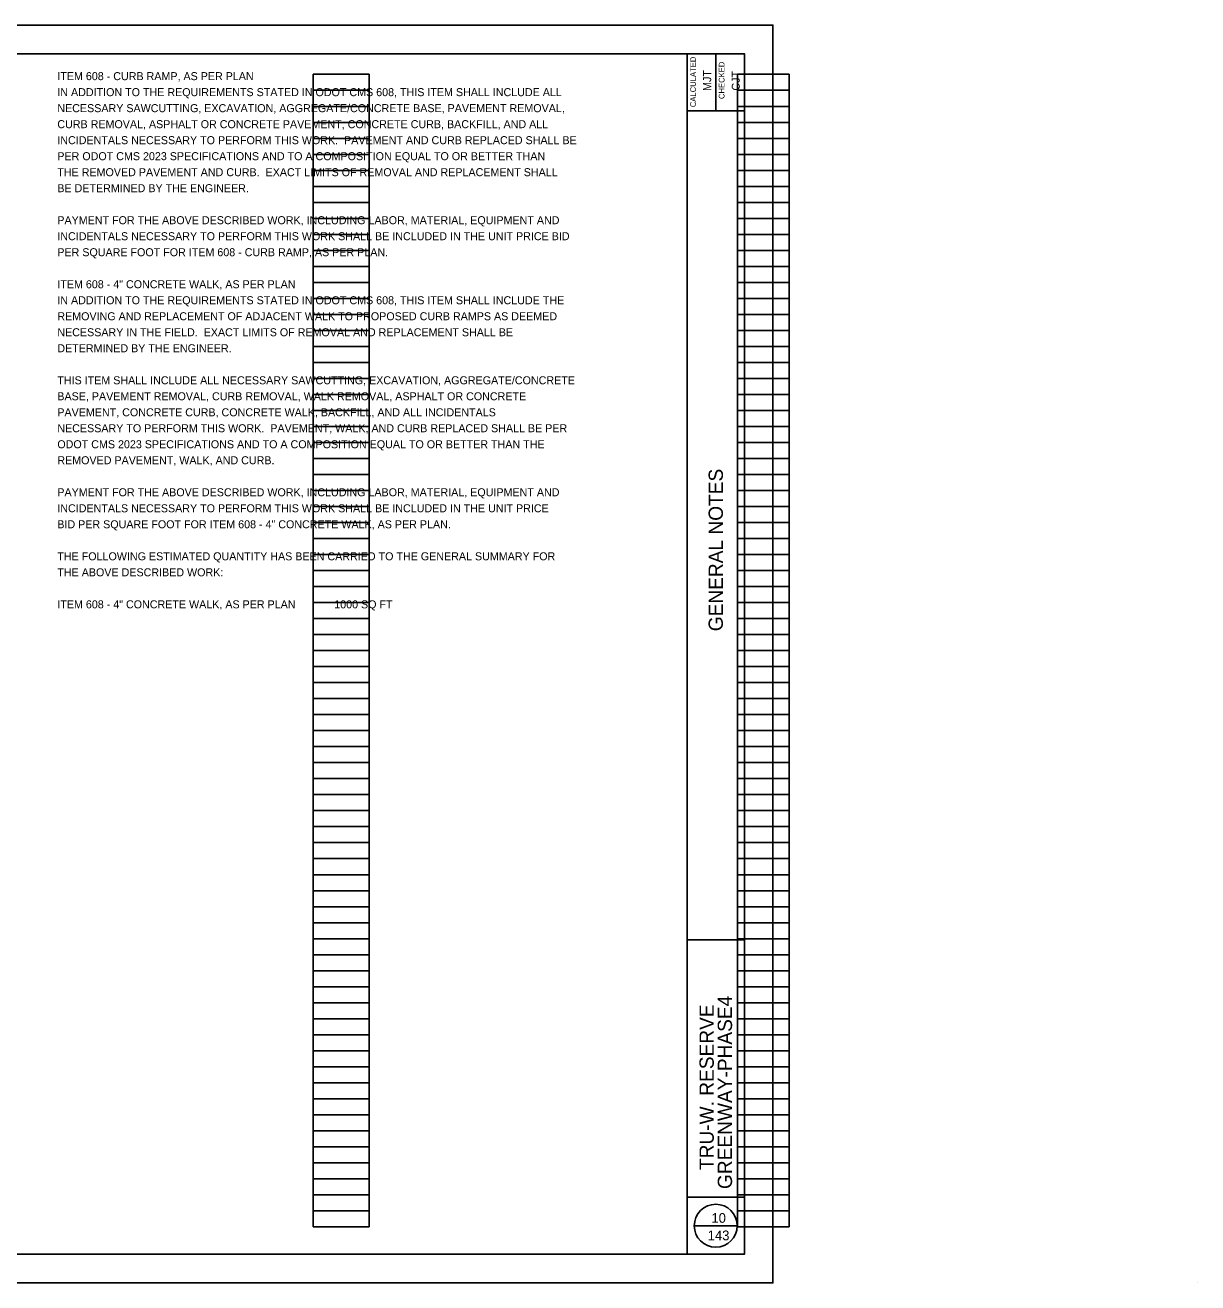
# Model space of a CAD drawing. Extents: x -16 to 195, y -13 to 9.
# Drawn here: x 48.79 to 69.29, y -12.91 to 9.09 of the extents above; entities that cross this region are included whole.
import ezdxf

# ---------------------------------------------------------------- set-up
doc = ezdxf.new("R2010")
doc.units = 0
for name, color, linetype in [('SH_Border', 7, 'Continuous'), ('SH_Cut_Line', 7, 'Continuous'), ('SH_Data', 7, 'Continuous'), ('TX_P_1', 7, 'Continuous')]:
    doc.layers.add(name, color=color, linetype=linetype)

msp = doc.modelspace()

# ---------------------------------------------------------------- linework, layer by layer
at = {"layer": 'SH_Border'}
for p, q in [((60.361, -12.407), (60.361, 8.593)), ((60.861, 8.593), (60.861, 7.593)), ((60.361, 7.593), (61.361, 7.593)), ((60.361, -6.907), (61.361, -6.907)), ((60.361, -11.407), (61.361, -11.407))]:
    msp.add_line(p, q, dxfattribs=at)
msp.add_lwpolyline([(29.861, 8.593), (61.361, 8.593), (61.361, -12.407), (29.861, -12.407)], close=True, dxfattribs=at)
at = {"layer": 'SH_Cut_Line'}
msp.add_lwpolyline([(27.861, -12.907), (61.861, -12.907), (61.861, 9.093), (27.861, 9.093)], close=True, dxfattribs=at)
at = {"layer": 'SH_Data'}
for p, q in [((53.822, -11.927), (53.822, 8.233)), ((53.822, 8.233), (54.802, 8.233)), ((54.802, -11.927), (54.802, 8.233)), ((61.242, -11.927), (61.242, 8.233)), ((61.242, 8.233), (62.142, 8.233)), ((62.142, -11.927), (62.142, 8.233)), ((53.822, 7.953), (54.802, 7.953)), ((61.242, 7.953), (62.142, 7.953)), ((53.822, 7.673), (54.802, 7.673)), ((61.242, 7.673), (62.142, 7.673)), ((53.822, 7.393), (54.802, 7.393)), ((61.242, 7.393), (62.142, 7.393)), ((53.822, 7.113), (54.802, 7.113)), ((61.242, 7.113), (62.142, 7.113)), ((53.822, 6.833), (54.802, 6.833)), ((61.242, 6.833), (62.142, 6.833)), ((53.822, 6.553), (54.802, 6.553)), ((61.242, 6.553), (62.142, 6.553)), ((53.822, 6.273), (54.802, 6.273)), ((61.242, 6.273), (62.142, 6.273)), ((53.822, 5.993), (54.802, 5.993)), ((61.242, 5.993), (62.142, 5.993)), ((53.822, 5.713), (54.802, 5.713)), ((61.242, 5.713), (62.142, 5.713)), ((53.822, 5.433), (54.802, 5.433)), ((61.242, 5.433), (62.142, 5.433)), ((53.822, 5.153), (54.802, 5.153)), ((61.242, 5.153), (62.142, 5.153)), ((53.822, 4.873), (54.802, 4.873)), ((61.242, 4.873), (62.142, 4.873)), ((53.822, 4.593), (54.802, 4.593)), ((61.242, 4.593), (62.142, 4.593)), ((53.822, 4.313), (54.802, 4.313)), ((61.242, 4.313), (62.142, 4.313)), ((53.822, 4.033), (54.802, 4.033)), ((61.242, 4.033), (62.142, 4.033)), ((53.822, 3.753), (54.802, 3.753)), ((61.242, 3.753), (62.142, 3.753)), ((53.822, 3.473), (54.802, 3.473)), ((61.242, 3.473), (62.142, 3.473)), ((53.822, 3.193), (54.802, 3.193)), ((61.242, 3.193), (62.142, 3.193)), ((53.822, 2.913), (54.802, 2.913)), ((61.242, 2.913), (62.142, 2.913)), ((53.822, 2.633), (54.802, 2.633)), ((61.242, 2.633), (62.142, 2.633)), ((53.822, 2.353), (54.802, 2.353)), ((61.242, 2.353), (62.142, 2.353)), ((53.822, 2.073), (54.802, 2.073)), ((61.242, 2.073), (62.142, 2.073)), ((53.822, 1.793), (54.802, 1.793)), ((61.242, 1.793), (62.142, 1.793)), ((53.822, 1.513), (54.802, 1.513)), ((61.242, 1.513), (62.142, 1.513)), ((53.822, 1.233), (54.802, 1.233)), ((61.242, 1.233), (62.142, 1.233)), ((53.822, 0.953), (54.802, 0.953)), ((61.242, 0.953), (62.142, 0.953)), ((53.822, 0.673), (54.802, 0.673)), ((61.242, 0.673), (62.142, 0.673)), ((53.822, 0.393), (54.802, 0.393)), ((61.242, 0.393), (62.142, 0.393)), ((53.822, 0.113), (54.802, 0.113)), ((61.242, 0.113), (62.142, 0.113)), ((53.822, -0.167), (54.802, -0.167)), ((61.242, -0.167), (62.142, -0.167)), ((53.822, -0.447), (54.802, -0.447)), ((61.242, -0.447), (62.142, -0.447)), ((53.822, -0.727), (54.802, -0.727)), ((61.242, -0.727), (62.142, -0.727)), ((53.822, -1.007), (54.802, -1.007)), ((61.242, -1.007), (62.142, -1.007)), ((53.822, -1.287), (54.802, -1.287)), ((61.242, -1.287), (62.142, -1.287)), ((53.822, -1.567), (54.802, -1.567)), ((61.242, -1.567), (62.142, -1.567)), ((53.822, -1.847), (54.802, -1.847)), ((61.242, -1.847), (62.142, -1.847)), ((53.822, -2.127), (54.802, -2.127)), ((61.242, -2.127), (62.142, -2.127)), ((53.822, -2.407), (54.802, -2.407)), ((61.242, -2.407), (62.142, -2.407)), ((53.822, -2.687), (54.802, -2.687)), ((61.242, -2.687), (62.142, -2.687)), ((53.822, -2.967), (54.802, -2.967)), ((61.242, -2.967), (62.142, -2.967)), ((53.822, -3.247), (54.802, -3.247)), ((61.242, -3.247), (62.142, -3.247)), ((53.822, -3.527), (54.802, -3.527)), ((61.242, -3.527), (62.142, -3.527)), ((53.822, -3.807), (54.802, -3.807)), ((61.242, -3.807), (62.142, -3.807)), ((53.822, -4.087), (54.802, -4.087)), ((61.242, -4.087), (62.142, -4.087)), ((53.822, -4.367), (54.802, -4.367)), ((61.242, -4.367), (62.142, -4.367)), ((53.822, -4.647), (54.802, -4.647)), ((61.242, -4.647), (62.142, -4.647)), ((53.822, -4.927), (54.802, -4.927)), ((61.242, -4.927), (62.142, -4.927)), ((53.822, -5.207), (54.802, -5.207)), ((61.242, -5.207), (62.142, -5.207)), ((53.822, -5.487), (54.802, -5.487)), ((61.242, -5.487), (62.142, -5.487)), ((53.822, -5.767), (54.802, -5.767)), ((61.242, -5.767), (62.142, -5.767)), ((53.822, -6.047), (54.802, -6.047)), ((61.242, -6.047), (62.142, -6.047)), ((53.822, -6.327), (54.802, -6.327)), ((61.242, -6.327), (62.142, -6.327)), ((53.822, -6.607), (54.802, -6.607)), ((61.242, -6.607), (62.142, -6.607)), ((53.822, -6.887), (54.802, -6.887)), ((61.242, -6.887), (62.142, -6.887)), ((53.822, -7.167), (54.802, -7.167)), ((61.242, -7.167), (62.142, -7.167)), ((53.822, -7.447), (54.802, -7.447)), ((61.242, -7.447), (62.142, -7.447)), ((53.822, -7.727), (54.802, -7.727)), ((61.242, -7.727), (62.142, -7.727)), ((53.822, -8.007), (54.802, -8.007)), ((61.242, -8.007), (62.142, -8.007)), ((53.822, -8.287), (54.802, -8.287)), ((61.242, -8.287), (62.142, -8.287)), ((53.822, -8.567), (54.802, -8.567)), ((61.242, -8.567), (62.142, -8.567)), ((53.822, -8.847), (54.802, -8.847)), ((61.242, -8.847), (62.142, -8.847)), ((53.822, -9.127), (54.802, -9.127)), ((61.242, -9.127), (62.142, -9.127)), ((53.822, -9.407), (54.802, -9.407)), ((61.242, -9.407), (62.142, -9.407)), ((53.822, -9.687), (54.802, -9.687)), ((61.242, -9.687), (62.142, -9.687)), ((53.822, -9.967), (54.802, -9.967)), ((61.242, -9.967), (62.142, -9.967)), ((53.822, -10.247), (54.802, -10.247)), ((61.242, -10.247), (62.142, -10.247)), ((53.822, -10.527), (54.802, -10.527)), ((61.242, -10.527), (62.142, -10.527)), ((53.822, -10.807), (54.802, -10.807)), ((61.242, -10.807), (62.142, -10.807)), ((53.822, -11.087), (54.802, -11.087)), ((61.242, -11.087), (62.142, -11.087)), ((53.822, -11.367), (54.802, -11.367)), ((61.242, -11.367), (62.142, -11.367)), ((53.822, -11.647), (54.802, -11.647)), ((61.242, -11.647), (62.142, -11.647)), ((53.822, -11.927), (54.802, -11.927)), ((60.486, -11.907), (61.236, -11.907)), ((61.242, -11.927), (62.142, -11.927)), ((69.29, -12.907), (69.29, -12.907))]:
    msp.add_line(p, q, dxfattribs=at)
msp.add_circle((60.861, -11.907), 0.375, dxfattribs=at)

# ---------------------------------------------------------------- texts
for s, height, p in [('CALCULATED', 0.1, (60.514, 7.658)), ('CHECKED', 0.1, (61.014, 7.801)), ('MJT', 0.14, (60.781, 7.942)), ('CJT', 0.14, (61.281, 7.949)), ('GENERAL NOTES', 0.25, (60.986, -1.509)), ('GREENWAY-PHASE4', 0.25, (61.146, -11.266)), ('TRU-W. RESERVE', 0.25, (60.827, -10.934))]:
    msp.add_text(s, height=height, rotation=90, dxfattribs=at).set_placement(p)
for s, p in [('10', (60.786, -11.857)), ('143', (60.721, -12.162))]:
    msp.add_text(s, height=0.17, dxfattribs=at).set_placement(p)
at = {"layer": 'TX_P_1'}
for s, p in [('ITEM 608 - CURB RAMP, AS PER PLAN', (49.349, 8.131)), ('IN ADDITION TO THE REQUIREMENTS STATED IN ODOT CMS 608, THIS ITEM SHALL INCLUDE ALL', (49.349, 7.851)), ('NECESSARY SAWCUTTING, EXCAVATION, AGGREGATE/CONCRETE BASE, PAVEMENT REMOVAL,', (49.349, 7.571)), ('CURB REMOVAL, ASPHALT OR CONCRETE PAVEMENT, CONCRETE CURB, BACKFILL, AND ALL', (49.349, 7.291)), ('INCIDENTALS NECESSARY TO PERFORM THIS WORK.  PAVEMENT AND CURB REPLACED SHALL BE', (49.349, 7.011)), ('PER ODOT CMS 2023 SPECIFICATIONS AND TO A COMPOSITION EQUAL TO OR BETTER THAN', (49.349, 6.731)), ('THE REMOVED PAVEMENT AND CURB.  EXACT LIMITS OF REMOVAL AND REPLACEMENT SHALL', (49.349, 6.451)), ('BE DETERMINED BY THE ENGINEER.', (49.349, 6.171)), ('PAYMENT FOR THE ABOVE DESCRIBED WORK, INCLUDING LABOR, MATERIAL, EQUIPMENT AND', (49.349, 5.611)), ('INCIDENTALS NECESSARY TO PERFORM THIS WORK SHALL BE INCLUDED IN THE UNIT PRICE BID', (49.349, 5.331)), ('PER SQUARE FOOT FOR ITEM 608 - CURB RAMP, AS PER PLAN.', (49.349, 5.051)), ('ITEM 608 - 4" CONCRETE WALK, AS PER PLAN', (49.349, 4.491)), ('IN ADDITION TO THE REQUIREMENTS STATED IN ODOT CMS 608, THIS ITEM SHALL INCLUDE THE', (49.349, 4.211)), ('REMOVING AND REPLACEMENT OF ADJACENT WALK TO PROPOSED CURB RAMPS AS DEEMED', (49.349, 3.931)), ('NECESSARY IN THE FIELD.  EXACT LIMITS OF REMOVAL AND REPLACEMENT SHALL BE', (49.349, 3.651)), ('DETERMINED BY THE ENGINEER.', (49.349, 3.371)), ('THIS ITEM SHALL INCLUDE ALL NECESSARY SAWCUTTING, EXCAVATION, AGGREGATE/CONCRETE', (49.349, 2.811)), ('BASE, PAVEMENT REMOVAL, CURB REMOVAL, WALK REMOVAL, ASPHALT OR CONCRETE', (49.349, 2.531)), ('PAVEMENT, CONCRETE CURB, CONCRETE WALK, BACKFILL, AND ALL INCIDENTALS', (49.349, 2.251)), ('NECESSARY TO PERFORM THIS WORK.  PAVEMENT, WALK, AND CURB REPLACED SHALL BE PER', (49.349, 1.972)), ('ODOT CMS 2023 SPECIFICATIONS AND TO A COMPOSITION EQUAL TO OR BETTER THAN THE', (49.349, 1.692)), ('REMOVED PAVEMENT, WALK, AND CURB.  ', (49.349, 1.412)), ('PAYMENT FOR THE ABOVE DESCRIBED WORK, INCLUDING LABOR, MATERIAL, EQUIPMENT AND', (49.349, 0.852)), ('INCIDENTALS NECESSARY TO PERFORM THIS WORK SHALL BE INCLUDED IN THE UNIT PRICE', (49.349, 0.572)), ('BID PER SQUARE FOOT FOR ITEM 608 - 4" CONCRETE WALK, AS PER PLAN.', (49.349, 0.292)), ('THE FOLLOWING ESTIMATED QUANTITY HAS BEEN CARRIED TO THE GENERAL SUMMARY FOR', (49.349, -0.268)), ('THE ABOVE DESCRIBED WORK:', (49.349, -0.548)), ('ITEM 608 - 4" CONCRETE WALK, AS PER PLAN             1000 SQ FT', (49.349, -1.108))]:
    msp.add_text(s, height=0.14, dxfattribs=at).set_placement(p)

doc.saveas('drawing.dxf')
